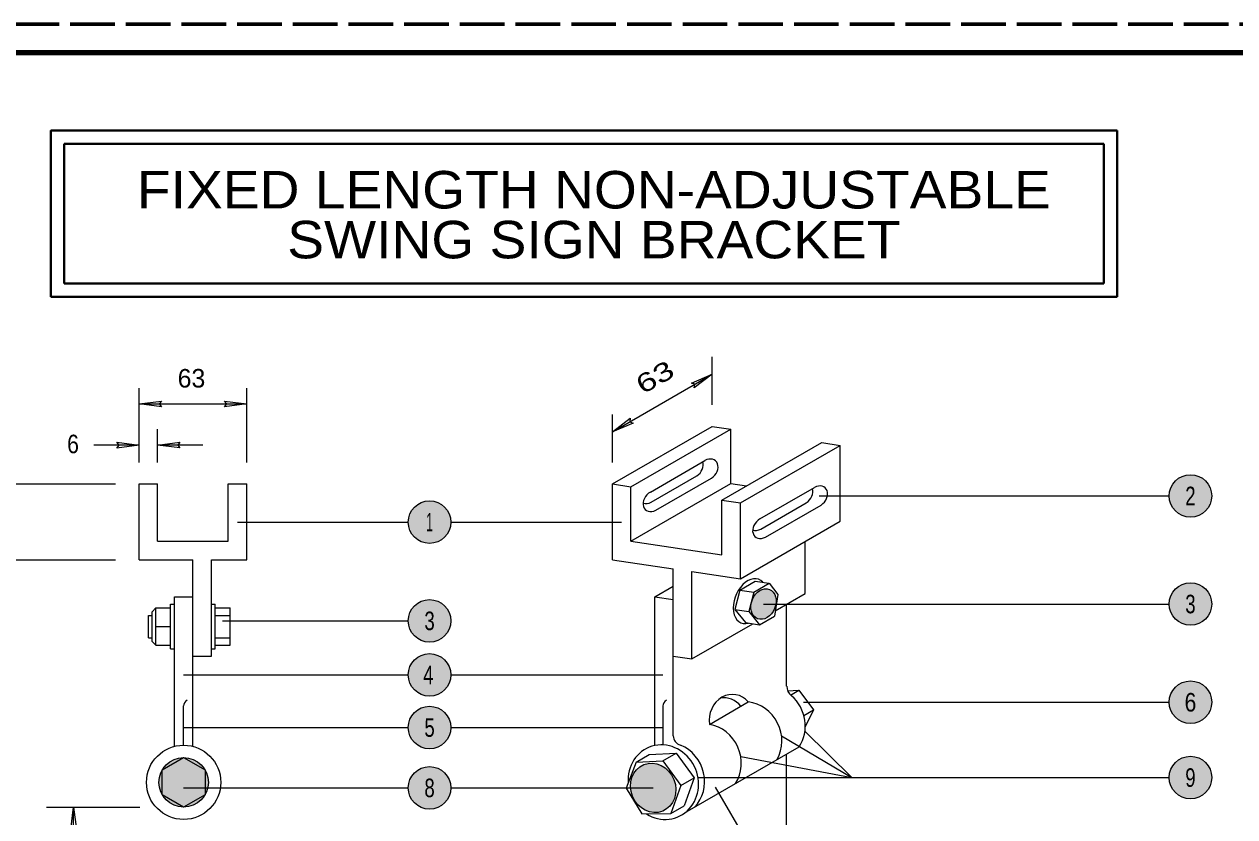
# Model space of a CAD drawing. Extents: x 312583 to 312853, y 144376 to 144586.
# Drawn here: x 312632.09 to 312681.01, y 144554.18 to 144586.22 of the extents above; entities that cross this region are included whole.
import ezdxf
from ezdxf.enums import TextEntityAlignment as Align

# ---------------------------------------------------------------- set-up
doc = ezdxf.new("R2010")
doc.units = 0
doc.header["$LTSCALE"] = 0.3
doc.linetypes.add('LONG_DASHED', pattern=[7.5, 6, -1.5])
for name, color, linetype, lineweight in [('1', 7, 'Continuous', 25), ('2', 7, 'Continuous', 13), ('63', 7, 'LONG_DASHED', 60)]:
    doc.layers.add(name, color=color, linetype=linetype, lineweight=lineweight)

msp = doc.modelspace()

# ---------------------------------------------------------------- hatches: boundary and pattern name
at = {"layer": '1'}
h = msp.add_hatch(color=256, dxfattribs=at)
edge = h.paths.add_edge_path()
edge.add_ellipse((312661.9638, 144562.7861), major_axis=(0.2406, 0.5922), ratio=0.761491, start_angle=0, end_angle=360)
for points in [[(312639.536, 144555.5781, 1), (312637.536, 144555.5781, 1)], [(312638.5361, 144556.5781), (312639.4021, 144556.0781), (312639.4021, 144555.0781), (312638.5361, 144554.5781), (312637.67, 144555.0781), (312637.67, 144556.0781)]]:
    msp.add_hatch(color=256, dxfattribs=at).paths.add_polyline_path(points)
h = msp.add_hatch(color=256, dxfattribs=at)
edge = h.paths.add_edge_path()
edge.add_ellipse((312657.5086, 144555.3532), major_axis=(-0.3821, 0.9403), ratio=0.8873452, start_angle=0, end_angle=360)
at = {"layer": '2'}
for points in [[(312680.0731, 144567.1545, 1), (312678.3539, 144567.1545, 1)], [(312649.3317, 144566.0951, 1), (312647.6125, 144566.0951, 1)], [(312680.0731, 144562.7861, 1), (312678.3539, 144562.7861, 1)], [(312649.3317, 144562.1052, 1), (312647.6125, 144562.1052, 1)], [(312649.3317, 144559.9198, 1), (312647.6125, 144559.9198, 1)], [(312680.0731, 144558.8159, 1), (312678.3539, 144558.8159, 1)], [(312649.3317, 144557.792, 1), (312647.6125, 144557.792, 1)], [(312680.0731, 144555.7704, 1), (312678.3539, 144555.7704, 1)], [(312649.3317, 144555.3532, 1), (312647.6125, 144555.3532, 1)]]:
    msp.add_hatch(color=256, dxfattribs=at).paths.add_polyline_path(points)

# ---------------------------------------------------------------- linework, layer by layer
at = {"layer": '1'}
for p, q in [((312655.858, 144567.6387), (312659.8879, 144569.9654)), ((312656.608, 144567.5276), (312660.638, 144569.8543)), ((312659.8879, 144569.9654), (312660.638, 144569.8543)), ((312660.638, 144567.6521), (312660.638, 144569.8543)), ((312660.2841, 144566.9831), (312664.3142, 144569.3099)), ((312664.3142, 144569.3099), (312665.0641, 144569.1988)), ((312657.3943, 144567.3135), (312659.5982, 144568.5859)), ((312636.7361, 144564.5753), (312636.7361, 144567.6387)), ((312636.7361, 144567.6387), (312637.4861, 144567.6387)), ((312637.4861, 144565.3253), (312637.4861, 144567.6387)), ((312640.3361, 144565.3253), (312640.3361, 144567.6387)), ((312640.3361, 144567.6387), (312641.0861, 144567.6387)), ((312641.0861, 144564.5753), (312641.0861, 144567.6387)), ((312655.858, 144564.5753), (312655.858, 144567.6387)), ((312655.858, 144567.6387), (312656.608, 144567.5276)), ((312656.608, 144565.3253), (312660.638, 144567.6521)), ((312657.4283, 144566.9002), (312659.2663, 144567.9613)), ((312657.6159, 144566.5754), (312659.8633, 144567.8729)), ((312660.638, 144567.6521), (312661.2785, 144567.5572)), ((312656.608, 144565.3253), (312656.608, 144567.5276)), ((312661.8204, 144566.2274), (312664.0244, 144567.4999)), ((312660.2841, 144564.7809), (312660.2841, 144566.9831)), ((312661.0341, 144563.8087), (312661.0341, 144566.8721)), ((312661.8545, 144565.8141), (312663.6924, 144566.8752)), ((312662.042, 144565.4893), (312664.2894, 144566.7868)), ((312637.4861, 144565.3253), (312640.3361, 144565.3253)), ((312656.608, 144565.3253), (312660.2841, 144564.7809)), ((312663.6493, 144563.2079), (312663.6493, 144565.3186)), ((312636.7361, 144564.5753), (312638.9111, 144564.5753)), ((312638.9111, 144557.0304), (312638.9111, 144564.5753)), ((312639.6611, 144564.5753), (312641.0861, 144564.5753)), ((312655.858, 144564.5753), (312658.3203, 144564.2107)), ((312658.3203, 144557.4623), (312658.3203, 144564.2107)), ((312659.0703, 144560.5642), (312659.0703, 144564.0996)), ((312659.0703, 144564.0996), (312661.0341, 144563.8087)), ((312661.0035, 144563.3496), (312661.6293, 144563.7109)), ((312661.6292, 144563.7109), (312662.185, 144563.6286)), ((312657.5703, 144563.0753), (312658.3203, 144563.5083)), ((312661.0035, 144563.3496), (312660.8034, 144562.5675)), ((312662.4389, 144562.5091), (312663.6493, 144563.2079)), ((312638.1611, 144563.0753), (312638.9111, 144563.0753)), ((312638.1611, 144557.0304), (312638.1611, 144563.0753)), ((312639.6611, 144562.7753), (312639.8111, 144562.7753)), ((312639.8111, 144560.9753), (312639.8111, 144562.7753)), ((312657.5703, 144563.0753), (312658.3203, 144562.9643)), ((312657.5703, 144557.0647), (312657.5703, 144563.0753)), ((312662.8993, 144559.4684), (312662.8993, 144562.7749)), ((312637.1111, 144561.4253), (312637.1111, 144562.3253)), ((312637.1111, 144562.3253), (312637.2611, 144562.3253)), ((312637.4111, 144562.6253), (312637.2611, 144562.4753)), ((312637.2611, 144561.2753), (312637.2611, 144562.4753)), ((312637.4111, 144561.1253), (312637.4111, 144562.6253)), ((312637.4111, 144562.6253), (312638.0111, 144562.6253)), ((312639.8111, 144562.6253), (312640.4111, 144562.6253)), ((312639.8111, 144562.3253), (312640.4111, 144562.3253)), ((312640.4111, 144561.1253), (312640.4111, 144562.6253)), ((312660.8034, 144562.5675), (312661.3696, 144562.4837)), ((312661.8044, 144561.9495), (312662.4029, 144562.2951)), ((312637.4111, 144561.8753), (312638.0111, 144561.8753)), ((312659.0703, 144560.5642), (312661.538, 144561.989)), ((312637.1111, 144561.4253), (312637.2611, 144561.4253)), ((312637.4111, 144561.1253), (312637.2611, 144561.2753)), ((312639.8111, 144561.4253), (312640.4111, 144561.4253)), ((312637.4111, 144561.1253), (312638.0111, 144561.1253)), ((312638.0111, 144560.9753), (312638.1611, 144560.9753)), ((312639.6611, 144560.9753), (312639.8111, 144560.9753)), ((312639.8111, 144561.1253), (312640.4111, 144561.1253)), ((312658.3203, 144560.6753), (312659.0703, 144560.5642)), ((312662.9376, 144559.2816), (312663.3958, 144559.3045)), ((312663.0562, 144559.1084), (312663.3958, 144559.3045)), ((312663.3958, 144559.3045), (312663.9792, 144558.504)), ((312659.7789, 144557.9202), (312661.347, 144558.8255)), ((312638.5361, 144557.0781), (312638.5361, 144558.666)), ((312657.9001, 144558.666), (312657.9001, 144557.0903)), ((312663.5939, 144558.2815), (312663.9792, 144558.504)), ((312663.9792, 144558.504), (312663.6527, 144557.826)), ((312658.8049, 144554.3579), (312663.4029, 144557.0125)), ((312656.8127, 144556.3944), (312657.3498, 144556.7045)), ((312657.3498, 144556.7045), (312658.4331, 144556.7586)), ((312657.896, 144556.4485), (312658.4331, 144556.7586)), ((312662.8993, 144549.8312), (312662.8993, 144556.7218)), ((312662.8993, 144556.0494), (312662.8993, 144556.7218)), ((312658.6266, 144555.446), (312659.1637, 144555.7561)), ((312658.2237, 144554.3156), (312658.7608, 144554.6257))]:
    msp.add_line(p, q, dxfattribs=at)
at = {"layer": '1', "lineweight": 158}
msp.add_lwpolyline([(312616.5, 144423.1446), (312616.5, 144585.0846), (312849, 144585.0846)], dxfattribs=at)
at = {"layer": '1', "lineweight": 13}
for points in [[(312659.0535, 144571.7204), (312659.8879, 144572.0751), (312659.1685, 144571.5212), (312659.1864, 144571.6701)], [(312637.6361, 144570.7624), (312636.7361, 144570.8724), (312637.6361, 144570.9924), (312637.5461, 144570.8724)], [(312640.1861, 144570.9824), (312641.0861, 144570.8724), (312640.1861, 144570.7524), (312640.2761, 144570.8724)], [(312656.6924, 144570.1031), (312655.858, 144569.7484), (312656.5774, 144570.3023), (312656.5595, 144570.1534)], [(312635.8361, 144569.3222), (312636.7361, 144569.2122), (312635.8361, 144569.0922), (312635.9261, 144569.2122)], [(312638.3861, 144569.1022), (312637.4861, 144569.2122), (312638.3861, 144569.3322), (312638.2961, 144569.2122)]]:
    msp.add_lwpolyline(points, close=True, dxfattribs=at)
at = {"layer": '1'}
for points in [[(312660.2841, 144566.9831), (312661.0341, 144566.8721), (312665.0641, 144569.1988)], [(312661.0341, 144563.8087), (312665.0641, 144566.1355), (312665.0641, 144569.1988)], [(312638.9111, 144560.6753), (312639.6611, 144560.6753), (312639.6611, 144564.5753)], [(312661.0035, 144563.3496), (312661.5697, 144563.2658), (312662.1955, 144563.6271)], [(312661.5697, 144563.2658), (312661.3696, 144562.4837), (312661.8044, 144561.9495)], [(312662.1955, 144563.6271), (312662.5489, 144563.1645), (312662.4029, 144562.2951)], [(312638.0111, 144560.9753), (312638.0111, 144562.7753), (312638.1611, 144562.7753)], [(312660.8034, 144562.5675), (312661.2382, 144562.0334), (312661.8044, 144561.9495)], [(312656.8127, 144556.3944), (312656.413, 144555.3379), (312657.0519, 144554.2988), (312658.2237, 144554.3156)], [(312656.8127, 144556.3944), (312657.896, 144556.4485), (312658.6266, 144555.446), (312658.2237, 144554.3156)], [(312658.4331, 144556.7586), (312659.1637, 144555.7561), (312658.7608, 144554.6257)]]:
    msp.add_lwpolyline(points, dxfattribs=at)
msp.add_lwpolyline([(312638.5361, 144556.5781), (312639.4021, 144556.0781), (312639.4021, 144555.0781), (312638.5361, 144554.5781), (312637.67, 144555.0781), (312637.67, 144556.0781)], close=True, dxfattribs=at)
for radius in [1.5, 1]:
    msp.add_circle((312638.536, 144555.5781), radius, dxfattribs=at)
for centre, radius, start, end in [((312663.397, 144559.4704), 0.4967, 180.22652, 231.68552), ((312658.7006, 144557.4553), 0.3804, 178.94586, 256.44003)]:
    msp.add_arc(centre, radius, start, end, dxfattribs=at)
for centre, major_axis, ratio, start_param, end_param in [((312659.1155, 144568.3065), (0.3145, 0.3553), 0.764015, 4.3716846, 5.8725332), ((312659.7125, 144568.2181), (0.3145, 0.3553), 0.764015, 4.3716846, 7.4201263), ((312664.1387, 144567.132), (0.3145, 0.3553), 0.764015, 4.3716846, 7.4201263), ((312657.5142, 144566.9494), (0.3145, 0.3553), 0.764015, 1.1518111, 4.2474694), ((312663.5417, 144567.2204), (0.3145, 0.3553), 0.764015, 4.3716846, 5.8725332), ((312657.3267, 144567.2742), (0.3145, 0.3553), 0.764015, 3.4232596, 4.2474694), ((312661.9404, 144565.8634), (0.3145, 0.3553), 0.764015, 1.1518111, 4.2474694), ((312661.7528, 144566.1882), (0.3145, 0.3553), 0.764015, 3.4232596, 4.2474694), ((312661.4164, 144562.9013), (-0.357, -0.8786), 0.649846, 2.8294508, 6.7628931), ((312638.9697, 144558.7057), (0.4336, 0.0397), 0.649846, 2.238563, 3.141509), ((312658.3337, 144558.7057), (0.4336, 0.0397), 0.649846, 2.238563, 3.141509), ((312660.6719, 144558.1228), (0.1817, 0.9986), 0.887345, 5.6414307, 8.2157378), ((312660.3493, 144557.9808), (0.1817, 0.9986), 0.887345, 5.600291, 6.6323001), ((312661.2818, 144557.3259), (-0.5733, 1.4109), 0.924918, 3.772746, 5.8235033), ((312662.2276, 144557.9316), (-0.5733, 1.4109), 0.924918, 3.6971351, 5.2200889), ((312659.6424, 144556.43), (-0.5733, 1.4109), 0.924918, 3.7094114, 5.7733759), ((312657.9148, 144555.5845), (-0.5733, 1.4109), 0.924918, 2.2297812, 7.5167148), ((312658.1596, 144555.6841), (-0.5733, 1.4109), 0.924918, 3.5253261, 5.5467497)]:
    msp.add_ellipse(centre, major_axis=major_axis, ratio=ratio, start_param=start_param, end_param=end_param, dxfattribs=at)
for centre, major_axis, ratio in [((312661.9638, 144562.7861), (0.2406, 0.5922), 0.761491), ((312657.5086, 144555.3532), (-0.3821, 0.9403), 0.887345)]:
    msp.add_ellipse(centre, major_axis=major_axis, ratio=ratio, dxfattribs=at)
at = {"layer": '2', "lineweight": 40}
for p, q in [((312676.2555, 144575.2061), (312676.2555, 144581.9239)), ((312633.7098, 144575.7451), (312633.7098, 144581.3849)), ((312633.7098, 144581.3849), (312675.7098, 144581.3849)), ((312675.7098, 144575.7451), (312675.7098, 144581.3849)), ((312633.7098, 144575.7451), (312675.7098, 144575.7451)), ((312633.1709, 144575.2061), (312676.2555, 144575.2061))]:
    msp.add_line(p, q, dxfattribs=at)
at = {"layer": '2'}
for p, q in [((312659.8879, 144570.8347), (312659.8879, 144572.7791)), ((312655.858, 144569.7484), (312659.8879, 144572.0751)), ((312636.7361, 144568.508), (312636.7361, 144571.5063)), ((312641.0861, 144568.508), (312641.0861, 144571.5063)), ((312636.7361, 144570.8724), (312641.0861, 144570.8724)), ((312655.858, 144568.508), (312655.858, 144570.4524)), ((312637.4861, 144568.508), (312637.4861, 144569.8556)), ((312636.7361, 144569.2122), (312634.9052, 144569.2122)), ((312639.317, 144569.2122), (312637.4861, 144569.2122)), ((312630.178, 144567.6387), (312635.7802, 144567.6387)), ((312664.2135, 144567.1545), (312678.3539, 144567.1545)), ((312640.7111, 144566.0951), (312647.6125, 144566.0951)), ((312649.3317, 144566.0951), (312656.233, 144566.0951)), ((312630.178, 144564.5753), (312635.7802, 144564.5753)), ((312661.9638, 144562.7861), (312678.3539, 144562.7861)), ((312640.1111, 144562.1052), (312647.6125, 144562.1052)), ((312638.5361, 144559.9198), (312647.6125, 144559.9198)), ((312649.3317, 144559.9198), (312657.9001, 144559.9198)), ((312663.574, 144558.8159), (312678.3539, 144558.8159)), ((312638.5361, 144557.792), (312647.6125, 144557.792)), ((312649.3317, 144557.792), (312657.9001, 144557.792)), ((312662.6933, 144557.4537), (312665.5337, 144555.7704)), ((312663.6393, 144557.6428), (312665.5337, 144555.7704)), ((312661.045, 144556.6168), (312665.5337, 144555.7704)), ((312638.5361, 144555.3532), (312647.6125, 144555.3532)), ((312649.3317, 144555.3532), (312657.5086, 144555.3532)), ((312659.3176, 144555.7704), (312678.3539, 144555.7704)), ((312660.0162, 144555.3804), (312661.5504, 144552.7571)), ((312632.9979, 144554.5781), (312636.7664, 144554.5781)), ((312634.0907, 144547.2985), (312634.0907, 144554.5781))]:
    msp.add_line(p, q, dxfattribs=at)
at = {"layer": '2', "lineweight": 40}
msp.add_lwpolyline([(312633.1709, 144575.2061), (312633.1709, 144581.9239), (312676.2555, 144581.9239)], dxfattribs=at)
at = {"layer": '2'}
msp.add_lwpolyline([(312633.9807, 144553.6781), (312634.0907, 144554.5781), (312634.2107, 144553.6781), (312634.0907, 144553.7681)], close=True, dxfattribs=at)
at = {"layer": '2', "lineweight": 25}
for centre in [(312679.2135, 144567.1545), (312648.4721, 144566.0951), (312679.2135, 144562.7861), (312648.4721, 144562.1052), (312648.4721, 144559.9198), (312679.2135, 144558.8159), (312648.4721, 144557.792), (312679.2135, 144555.7704), (312648.4721, 144555.3532)]:
    msp.add_circle(centre, 0.8596, dxfattribs=at)
at = {"layer": '63'}
msp.add_line((312851.75, 144586.2246), (312583.526, 144586.2246), dxfattribs=at)

# ---------------------------------------------------------------- texts
at = {"layer": '2'}
for s, height, width, p in [('FIXED LENGTH NON-ADJUSTABLE', 1.516, 1.1, (312655.1114, 144578.7753)), ('SWING SIGN BRACKET', 1.516, 1.1, (312655.1114, 144576.7591)), ('2', 0.75, 0.75, (312679.2135, 144566.7795)), ('1', 0.75, 0.5, (312648.472, 144565.7201)), ('3', 0.75, 0.75, (312679.2135, 144562.4111)), ('3', 0.75, 0.75, (312648.472, 144561.7302)), ('4', 0.75, 0.75, (312648.4206, 144559.5448)), ('6', 0.75, 0.85, (312679.2135, 144558.4409)), ('5', 0.75, 0.75, (312648.472, 144557.417)), ('9', 0.75, 0.75, (312679.2135, 144555.3954)), ('8', 0.75, 0.75, (312648.472, 144554.9782))]:
    msp.add_text(s, height=height, dxfattribs=dict(at, width=width)).set_placement(p, align=Align.CENTER)
at = {"layer": '2', "width": 1.4}
msp.add_text('63', height=0.75, rotation=30, dxfattribs=at).set_placement((312657.0876, 144571.2464))
at = {"layer": '2'}
msp.add_text('63', height=0.75, dxfattribs=at).set_placement((312638.295, 144571.5377))
at = {"layer": '2', "width": 0.85}
msp.add_text('6', height=0.75, dxfattribs=at).set_placement((312633.8303, 144568.8808))

doc.saveas('drawing.dxf')
